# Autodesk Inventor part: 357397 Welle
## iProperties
Created: 2006-03
Part Number: 357397 Welle
Material: 1.0711
Document SubType Name: Modeling
Manufacturer: Standard
Standards Organization: Custom
Description: Schaltwelle
Cost Center: 0,587 kg
Authority: 74724 mm^3
Density: 7.86 g/cm^3
Title: Schaltwelle
HalbzeugNorm: DIN 176
Zweck: Vorkontakt HSLT
Abmessung: Skt. 22
SaveDate: 2006-11-02
SaveTime: 23:35
TotalMass: 0,587 kg
TotalVolume: 74724 mm^3
Author: T.Messerschmitt
Revision Number: 357397
Keywords: 266417
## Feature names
1. Extrusion1
2. Extrusion2
3. Extrusion5
4. Fase_0.5x45° [Chamfer]
5. Bohrung_Ø5 [Hole]
6. Drehung1 [Revolution]
